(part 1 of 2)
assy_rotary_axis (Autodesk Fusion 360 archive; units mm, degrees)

design "assy_rotary_axis" references "circuit_mount_stepper_simple", "PP_ACTU_N17-Stepper", "PP_BRNG_6808-40x52x7", "rotary_barrel", "HW_M3x20-SHCS", "PP_TRNS_GT2-Pulley-20T-6mm", "HW_M5x10-SHCS", "PP_SWTC_Omron-V154", "HW_M3-Washer", "HW_M3x8-FHCS", "HW_M3x50-SHCS"
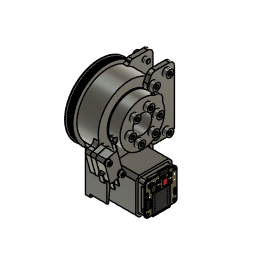
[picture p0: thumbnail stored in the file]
parameter "p_teeth" = 2
parameter "pd_pinion" = 12.7324 (= "nt_pinion * p_teeth / PI")
parameter "pd_drive" = 79.5775 (= "nt_drive * p_teeth / PI")
parameter "c_dist_manuel" = 58
parameter "d63" = 60
sketch "Sketch1" plane through (0, 0, 0) normal (0, 1, 0) x axis (1, 0, 0)
  line L1 (7, 26) -> (0, 26)
  line L2 (7, 20) -> (7, 26)
  line L3 (0, 20) -> (7, 20)
  line L4 (0, 26) -> (0, 20)
  line L5 (25, 20) -> (18, 20)
  line L6 (25, 26) -> (25, 20)
  line L7 (18, 26) -> (25, 26)
  line L8 (18, 20) -> (18, 26)
  line L9 (22.786, 0) -> (0, 0)
  line L10 (-50.1, 36.85) -> (19.9, 36.85)
  line L11 (-50.1, 79.15) -> (-50.1, 36.85)
  line L12 (19.9, 79.15) -> (-50.1, 79.15)
  line L13 (19.9, 36.85) -> (19.9, 79.15)
  line L14 (-50.1, 58) -> (19.9, 58)
  line L15 (25, 37.05) -> (25, 26.05)
  line L16 (0, 26.05) -> (25, 26.05)
  line L17 (25, 37.05) -> (0, 37.05)
  line L18 (0, 37.05) -> (0, 26.05)
  line L19 (7.5, 25.05) -> (6.5, 26.05)
  line L20 (17.5, 25.05) -> (7.5, 25.05)
  line L21 (18.5, 26.05) -> (17.5, 25.05)
  point P6 (18, 20)
  point P1 (0, 0)
  point P10 (0, 0)
  point P16 (19.9, 58)
  point P17 (-50.1, 58)
  point P21 (0, 37.05)
  point P23 (0, 37.05)
  point P18 (25, 26.05)
  point P19 (25, 26.05)
  point P8 (25, 26)
  point P2 (0, 26)
  point P24 (6.5, 26.05)
  point P27 (18.5, 26.05)
  point P4 (7, 20)
  point P5 (0, 20)
  point P12 (19.9, 36.85)
  point P15 (19.9, 79.15)
  point P13 (-50.1, 36.85)
  point P9 (18, 26)
  point P20 (0, 26.05)
  point P22 (25, 37.05)
  point P3 (7, 26)
  horizontal L1
  vertical L2
  horizontal L3
  horizontal L5
  vertical L6
  horizontal L7
  vertical L8
  equal L3 L5
  coincident L3 P6
  coincident P1 L4
  equal L2 L8
  coincident P1 P10
  horizontal L9
  horizontal L10
  vertical L11
  horizontal L12
  midpoint L13 P16
  midpoint L11 P17
  vertical L4
  vertical L15
  vertical L13
  perpendicular L2 L16
  perpendicular L13 L17
  perpendicular L10 L18
  coincident P21 P23
  coincident P18 P19
  coincident P8 L15
  coincident P2 L18
  coincident L16 P24
  parallel L1 L20
  coincident L16 P27
  dimension "d5" distance P4 P5 = 7
  dimension "d6" distance P1 L1 = 26 (= "( 52 / 2 ) * 1 mm")
  dimension "d7" distance P1 P5 = 20 (= "( 40 / 2 ) * 1 mm")
  dimension "d32" distance P12 P15 = 42.3
  dimension "d33" distance P1 P17 = 58 (= "c_dist_manuel")
  dimension "d34" distance P12 P13 = 70
  dimension "d61" distance P4 P6 = 11
  dimension "d140" distance P9 L16 = 0.05
  dimension "d141" distance P20 P23 = 11
  dimension "d150" distance L13 P22 = 5.1
  dimension "d259" angle L19 L20 = 45
  dimension "d260" distance P3 P24 = 0.5
  dimension "d261" distance L16 L20 = 1
  dimension "d262" angle L20 L21 = 45
  dimension "d263" distance L8 P27 = 0.5 (= "d260")
  dimension "d357" distance P18 L18 = 25
revolve "Revolve6" sketch "Sketch1" AlongAngle 360
sketch "Sketch6" plane through (0, 0, 0) normal (1, 0, 0) x axis (0, 1, 0)
  line L1 (21.15, -36.85) -> (-21.15, -36.85)
  line L2 (21.15, -79.15) -> (21.15, -36.85)
  line L3 (-21.15, -79.15) -> (21.15, -79.15)
  line L4 (-21.15, -36.85) -> (-21.15, -79.15)
  line L5 (21.15, -79.15) -> (-21.15, -36.85)
  line L6 (-21.15, -79.15) -> (21.15, -36.85)
  line L7 (0, 0) -> (0, -58)
  line L8 (15.5, -42.5) -> (-15.5, -42.5)
  line L9 (15.5, -73.5) -> (15.5, -42.5)
  line L10 (-15.5, -73.5) -> (15.5, -73.5)
  line L11 (-15.5, -42.5) -> (-15.5, -73.5)
  line L12 (15.4393, -40.5607) -> (-15.5, -42.5)
  line L13 (17.3786, -71.5) -> (-15.5, -42.5)
  line L14 (-13.5607, -73.4393) -> (-15.5, -42.5)
  line L15 (-15.5, -42.5) -> (12.1767, -76.5)
  line L16 (-15.5, -42.5) -> (-18.6616, -73.3384)
  line L17 (-15.5, -42.5) -> (15.3384, -45.6616)
  line L18 (12.4957, -82.7149) -> (-25.4068, -78.8291)
  line L19 (-21.0864, -36.6881) -> (-25.4068, -78.8291)
  line L20 (27, -33.674) -> (-21.0864, -36.6881)
  line L21 (-27, -78.6657) -> (-25.4068, -78.8291)
  line L22 (-27, -25.3713) -> (-27, -78.6657)
  line L23 (24.7149, -70.4957) -> (22.4249, -33.9608)
  line L24 (27, -25.3713) -> (27, -66.8875)
  line L25 (-43.1948, -16.2223) -> (-37.449, -37.6658)
  line L26 (-33.2458, -13.5564) -> (-43.1948, -16.2223)
  line L27 (-27.5, -35) -> (-33.2458, -13.5564)
  line L28 (-37.449, -37.6658) -> (-27.5, -35)
  line L29 (-46.8691, -14.101) -> (-39.5704, -41.3401)
  line L30 (-35.373, -11.0206) -> (-46.8691, -14.101)
  line L31 (-27, -37.9719) -> (-39.5704, -41.3401)
  line L32 (5.2029, -61.6685) -> (32.5183, -22.9283)
  line L33 (-5.2029, -61.6685) -> (-32.5183, -22.9283)
  line L34 (-31.1245, -9.8822) -> (-35.373, -11.0206)
  line L35 (-23.8258, -37.1213) -> (-31.1245, -9.8822)
  line L36 (-27, -37.9719) -> (-23.8258, -37.1213)
  arc A1 centre (-15.5, -42.5) radius 32.75 clockwise from (17.1859, -40.4512) to (17.0792, -45.8401)
  arc A2 centre (15.3384, -45.6616) radius 1.75 clockwise from (17.0792, -45.8401) to (13.5975, -45.4832)
  arc A3 centre (-15.5, -42.5) radius 29.25 clockwise from (13.6927, -40.6702) to (13.5975, -45.4832)
  arc A4 centre (15.4393, -40.5607) radius 1.75 clockwise from (13.6927, -40.6702) to (17.1859, -40.4512)
  arc A5 centre (-15.5, -42.5) radius 31 clockwise from (15.4393, -40.5607) to (15.3384, -45.6616)
  arc A6 centre (-15.5, -42.5) radius 33.0203 clockwise from (9.2638, -64.3425) to (5.3458, -68.1085)
  arc A7 centre (-1.6616, -59.5) radius 11.1 clockwise from (5.3458, -68.1085) to (-8.6691, -50.8915)
  arc A8 centre (-15.5, -42.5) radius 10.8203 clockwise from (-7.3852, -49.6575) to (-8.6691, -50.8915)
  arc A9 centre (0.9393, -57) radius 11.1 clockwise from (-7.3852, -49.6575) to (9.2638, -64.3425)
  arc A10 centre (-15.5, -42.5) radius 21.9203 clockwise from (0.9393, -57) to (-1.6616, -59.5)
  arc A11 centre (-15.5, -42.5) radius 45.5906 clockwise from (18.691, -72.6576) to (13.2815, -77.8572)
  arc A12 centre (12.1767, -76.5) radius 1.75 clockwise from (13.2815, -77.8572) to (11.0719, -75.1428)
  arc A13 centre (-15.5, -42.5) radius 42.0906 clockwise from (16.0661, -70.3424) to (11.0719, -75.1428)
  arc A14 centre (17.3786, -71.5) radius 1.75 clockwise from (16.0661, -70.3424) to (18.691, -72.6576)
  arc A15 centre (-15.5, -42.5) radius 43.8406 clockwise from (17.3786, -71.5) to (12.1767, -76.5)
  arc A16 centre (-15.5, -42.5) radius 32.75 clockwise from (-13.4512, -75.1859) to (-18.8401, -75.0792)
  arc A17 centre (-18.6616, -73.3384) radius 1.75 clockwise from (-18.8401, -75.0792) to (-18.4832, -71.5975)
  arc A18 centre (-15.5, -42.5) radius 29.25 clockwise from (-13.6702, -71.6927) to (-18.4832, -71.5975)
  arc A19 centre (-13.5607, -73.4393) radius 1.75 clockwise from (-13.6702, -71.6927) to (-13.4512, -75.1859)
  arc A20 centre (-15.5, -42.5) radius 31 clockwise from (-13.5607, -73.4393) to (-18.6616, -73.3384)
  circle C1 centre (-15.5, -42.5) radius 1.75
  arc A21 centre (-15.5, -42.5) radius 49 clockwise from (24.7149, -70.4957) to (12.4957, -82.7149)
  arc A22 centre (-15.5, -42.5) radius 49 clockwise from (27, -66.8875) to (24.7149, -70.4957)
  circle C2 centre (0, 0) radius 39.7887
  circle C3 centre (0, 0) radius 26.05
  circle C4 centre (0, 0) radius 37.05
  circle C5 centre (-27.5, -35) radius 1.25
  circle C6 centre (-43.1948, -16.2223) radius 1.25
  circle C7 centre (-43.1948, -16.2223) radius 3
  circle C8 centre (0, -58) radius 6.3662
  circle C9 centre (-27.5, -35) radius 3
  circle C10 centre (-27.5, -35) radius 1.75
  circle C11 centre (-43.1948, -16.2223) radius 1.75
  point P6 (0, -58)
  point P8 (0, -58)
  point P7 (0, 0)
  point P9 (0, 0)
  point P12 (15.5, -73.5)
  point P10 (-15.5, -42.5)
  point P13 (-15.5, -73.5)
  point P20 (-15.5, -42.5)
  point P27 (-15.5, -42.5)
  point P34 (-15.5, -42.5)
  point P41 (-15.5, -42.5)
  point P43 (-15.5, -42.5)
  point P18 (15.4393, -40.5607)
  point P44 (15.4393, -40.5607)
  point P42 (-15.5, -42.5)
  point P45 (-15.5, -42.5)
  point P32 (17.3786, -71.5)
  point P46 (17.3786, -71.5)
  point P47 (-15.5, -42.5)
  point P39 (-13.5607, -73.4393)
  point P48 (-13.5607, -73.4393)
  point P11 (15.5, -42.5)
  point P25 (0.9393, -57)
  point P33 (12.1767, -76.5)
  point P49 (12.1767, -76.5)
  point P50 (-15.5, -42.5)
  point P40 (-18.6616, -73.3384)
  point P51 (-18.6616, -73.3384)
  point P52 (-15.5, -42.5)
  point P19 (15.3384, -45.6616)
  point P53 (15.3384, -45.6616)
  point P54 (-15.5, -42.5)
  point P26 (-1.6616, -59.5)
  point P57 (-15.5, -42.5)
  point P60 (-21.0864, -36.6881)
  point P64 (22.4249, -33.9608)
  point P66 (19.1482, -77.1482)
  point P58 (24.7149, -70.4957)
  point P65 (24.7149, -70.4957)
  point P61 (27, -33.674)
  point P69 (-15.5, -42.5)
  point P67 (27, -66.8875)
  point P70 (27, -66.8875)
  point P71 (0, 0)
  point P68 (27, -25.3713)
  point P63 (-27, -25.3713)
  point P59 (-21.0864, -36.6881)
  point P76 (-27.5, -35)
  point P77 (-27.5, -35)
  point P74 (-43.1948, -16.2223)
  point P78 (-43.1948, -16.2223)
  point P80 (-35.373, -11.0206)
  point P83 (-27, -37.9719)
  point P84 (0, -58)
  point P85 (32.5183, -22.9283)
  point P86 (5.2029, -61.6685)
  point P87 (-32.5183, -22.9283)
  point P88 (-5.2029, -61.6685)
  point P4 (21.15, -79.15)
  point P5 (-21.15, -79.15)
  point P1 (0, 0)
  point P73 (-37.449, -37.6658)
  point P75 (-33.2458, -13.5564)
  point P81 (-43.1948, -16.2223)
  horizontal L1
  perpendicular L1 L2
  parallel L1 L3
  parallel L2 L4
  coincident L5 P6
  coincident L6 P6
  equal L2 L3
  coincident P6 P8
  coincident P7 P9
  vertical L7
  horizontal L8
  vertical L9
  horizontal L10
  vertical L11
  coincident L5 P12
  coincident L5 P10
  coincident L6 P13
  tangent A1 A2
  tangent A2 A3
  tangent A3 A4
  tangent A1 A4
  coincident P10 P20
  tangent A6 A7
  tangent A7 A8
  tangent A8 A9
  tangent A6 A9
  coincident P20 P27
  tangent A11 A12
  tangent A12 A13
  tangent A13 A14
  tangent A11 A14
  coincident P27 P34
  tangent A16 A17
  tangent A17 A18
  tangent A18 A19
  tangent A16 A19
  coincident P34 P41
  concentric A11 C1
  coincident P34 P43
  coincident P18 P44
  coincident P42 P45
  coincident P32 P46
  coincident P41 P47
  coincident P39 P48
  coincident P11 A5
  coincident P6 A10
  coincident P13 A20
  coincident P12 A15
  coincident P25 L13
  coincident P33 P49
  coincident P20 P50
  coincident P40 P51
  coincident P27 P52
  coincident P19 P53
  coincident P20 P54
  equal A4 A14
  equal A14 A19
  equal A19 C1
  coincident P26 L15
  perpendicular L12 L14
  perpendicular L16 L17
  parallel L17 L18
  coincident P42 P57
  parallel L16 L19
  coincident L19 P60
  parallel L12 L20
  perpendicular L19 L21
  vertical L22
  coincident L20 P64
  perpendicular L20 L23
  midpoint A21 P66
  coincident L5 P66
  coincident P58 P65
  vertical L24
  coincident P61 L24
  coincident P57 P69
  coincident P67 P70
  coincident P7 P71
  coincident P68 C4
  coincident P63 C4
  coincident P59 P60
  perpendicular L25 L26
  parallel L25 L27
  parallel L26 L28
  coincident P76 P77
  coincident P74 P78
  equal C5 C6
  perpendicular L26 L29
  coincident C4 P80
  perpendicular L29 L30
  concentric C6 C7
  coincident L22 P83
  perpendicular L29 L31
  coincident P6 P84
  coincident C2 P85
  coincident C8 P86
  tangent C8 L32
  tangent C2 L32
  coincident C2 P87
  coincident C8 P88
  tangent C8 L33
  tangent C2 L33
  parallel L30 L34
  parallel L31 L36
  parallel L27 L35
  concentric C5 C9
  tangent L31 C9
  tangent L35 C9
  concentric C9 C10
  concentric C7 C11
  equal C10 C11
  dimension "d151" distance P6 P7 = 58 (= "c_dist_manuel")
  dimension "d152" distance P4 P5 = 42.3
  dimension "d153" distance P10 P11 = 31
  dimension "d154" diameter C1 = 3.5
  dimension "d156" radius A9 = 11.1 (= "( 22.2 / 2 ) * 1 mm")
  dimension "d157" distance P6 P25 = 1
  dimension "d158" distance P6 P26 = 1.5
  dimension "d159" angle L15 L17 = 45
  dimension "d160" radius A21 = 49
  dimension "d161" distance P40 L18 = 6.15 (= "( ( 42.3 - 31 ) / 2 ) * 1 mm + 0.5 mm")
  dimension "d162" distance L16 L19 = 6.15 (= "d161")
  dimension "d163" angle L12 L13 = 45
  dimension "d164" distance P20 L20 = 6.15 (= "d161")
  dimension "d166" distance P9 L22 = 27
  dimension "d167" distance P1 L24 = 27
  dimension "d264" diameter C2 = 79.5775 (= "pd_drive")
  dimension "d286" distance P73 P74 = 22.2
  dimension "d288" distance P74 P75 = 10.3
  dimension "d289" diameter C6 = 2.5
  dimension "d290" angle L7 L27 = 15
  dimension "d291" distance P71 P77 = 35
  dimension "d292" distance P1 P77 = 27.5
  dimension "d293" diameter C7 = 6
  dimension "d294" distance L29 P81 = 3
  dimension "d295" distance L30 P81 = 3 (= "d294")
  dimension "d303" distance P73 L31 = 3 (= "d294")
  dimension "d435" diameter C8 = 12.7324 (= "( 20 * 2 / PI ) * 1 mm")
  dimension "d439" diameter C11 = 3.5
extrude "Extrude8" add sketch "Sketch6" profile of L19 L20 L21 L22 L23 L24 A22 C4 to an object
extrude "Extrude20" cut sketch "Sketch6" profile of L20 C4 to an object
extrude "Extrude19" add sketch "Sketch6" profile of A1 A2 A3 A4 A6 A7 A8 A9 A11 A12 A13 A14 A16 A17 A18 A19 C1 L18 A21 L19 L20 L23 along normal blind 5
chamfer "Chamfer4" distance 1.5
extrude "Extrude21" sketch "Sketch6" profile of L22 C4 C5 C6 L29 L30 L31 blind -6
extrude "Extrude22" sketch "Sketch6" profile of L22 C5 to an object offset 0.5
chamfer "Chamfer5" distance 1.25
chamfer "Chamfer6" distance 0.5
sketch "Sketch10" plane through (0, 0, 0) normal (-1, 0, 0) x axis (0, -1, 0)
  line L1 (27, -78.6657) -> (-12.4957, -82.7149)
  line L2 (27, -25.3713) -> (27, -78.6657)
  line L3 (-27, -66.8875) -> (-27, -25.3713)
  line L4 (-27, 50) -> (-47, 50)
  line L5 (-27, -90) -> (-27, 50)
  line L6 (-47, -90) -> (-27, -90)
  line L7 (-47, 50) -> (-47, -90)
  line L8 (-37, -90) -> (-37, 50)
  line L9 (-21.362, 37) -> (-47, 37)
  line L10 (-47, -37) -> (-27, -37)
  line L11 (-21.362, -37) -> (-27, -37)
  line L12 (-13.275, -22.993) -> (-21.362, -37)
  line L13 (-27, 0) -> (0, 0)
  line L14 (-21.362, 37) -> (-13.275, 22.993)
  circle C1 centre (15.5, -42.5) radius 3.25
  arc A1 centre (15.5, -42.5) radius 40.5906 clockwise from (-10.125, -73.9795) to (-14.9412, -69.3502)
  arc A2 centre (-12.1767, -76.5) radius 3.25 clockwise from (-10.125, -73.9795) to (-14.2284, -79.0205)
  arc A3 centre (15.5, -42.5) radius 47.0906 clockwise from (-14.2284, -79.0205) to (-19.8159, -73.6498)
  arc A4 centre (-17.3786, -71.5) radius 3.25 clockwise from (-19.8159, -73.6498) to (-14.9412, -69.3502)
  arc A5 centre (0, 0) radius 37.05 clockwise from (-27, -25.3713) to (27, -25.3713)
  arc A6 centre (15.5, -42.5) radius 49 clockwise from (-12.4957, -82.7149) to (-27, -66.8875)
  arc A7 centre (1.6616, -59.5) radius 11.1 clockwise from (8.6691, -50.8915) to (-5.3458, -68.1085)
  arc A8 centre (15.5, -42.5) radius 33.0203 clockwise from (-5.3458, -68.1085) to (-9.2638, -64.3425)
  arc A9 centre (-0.9393, -57) radius 11.1 clockwise from (-9.2638, -64.3425) to (7.3852, -49.6575)
  arc A10 centre (15.5, -42.5) radius 10.8203 clockwise from (8.6691, -50.8915) to (7.3852, -49.6575)
  arc A11 centre (15.5, -42.5) radius 27.75 clockwise from (-12.1053, -45.3302) to (-12.1956, -40.764)
  arc A12 centre (-15.3384, -45.6616) radius 3.25 clockwise from (-12.1053, -45.3302) to (-18.5714, -45.9931)
  arc A13 centre (15.5, -42.5) radius 34.25 clockwise from (-18.5714, -45.9931) to (-18.6829, -40.3574)
  arc A14 centre (-15.4393, -40.5607) radius 3.25 clockwise from (-18.6829, -40.3574) to (-12.1956, -40.764)
  arc A15 centre (13.5607, -73.4393) radius 3.25 clockwise from (13.3574, -76.6829) to (13.764, -70.1956)
  arc A16 centre (15.5, -42.5) radius 27.75 clockwise from (18.3302, -70.1053) to (13.764, -70.1956)
  arc A17 centre (18.6616, -73.3384) radius 3.25 clockwise from (18.3302, -70.1053) to (18.9931, -76.5714)
  arc A18 centre (15.5, -42.5) radius 34.25 clockwise from (18.9931, -76.5714) to (13.3574, -76.6829)
  circle C2 centre (0, 0) radius 26.55
  circle C3 centre (-37, -30) radius 2.75
  circle C4 centre (-37, 0) radius 2.75
  circle C5 centre (-37, 30) radius 2.75
  circle C6 centre (-21.1923, -24.7061) radius 2.75
  circle C7 centre (-21.1923, -24.7061) radius 2.2
  circle C8 centre (-21.1923, -24.7061) radius 6
  circle C9 centre (-21.1923, 24.7061) radius 2.75
  circle C10 centre (-21.1923, 24.7061) radius 2.2
  circle C11 centre (-21.1923, 24.7061) radius 6
  circle C12 centre (-37, 30) radius 4.5
  point P12 (-27, -25.3713)
  point P37 (-37, 50)
  point P38 (-37, -90)
  point P39 (-47, 37)
  point P40 (-27, -37)
  point P41 (-47, -37)
  point P42 (-37, -30)
  point P43 (-37, 0)
  point P44 (-37, 30)
  point P48 (-13.275, -22.993)
  point P1 (0, 0)
  point P49 (0, 0)
  point P50 (-27, 0)
  point P55 (-13.275, 22.993)
  point P33 (-47, 50)
  point P34 (-27, 50)
  point P13 (0, 0)
  horizontal L4
  vertical L5
  horizontal L6
  vertical L7
  coincident P12 L5
  midpoint L4 P37
  midpoint L6 P38
  coincident L7 P39
  perpendicular L7 L9
  coincident L5 P40
  coincident L7 P41
  perpendicular L7 L10
  coincident L8 P42
  coincident L8 P43
  coincident L8 P44
  equal C4 C5
  equal C3 C4
  concentric C6 C7
  perpendicular L5 L11
  coincident C2 P48
  coincident P1 L12
  coincident P1 P49
  coincident L5 P50
  perpendicular L5 L13
  concentric C7 C8
  equal C3 C6
  symmetric C6 L13 C9
  symmetric C7 L13 C10
  symmetric L13 C8 C11
  coincident C2 P55
  tangent C11 L14
  coincident P1 L14
  tangent C2 C8
  tangent L12 C8
  concentric C5 C12
  coincident P43 L13
  dimension "d358" distance P33 P34 = 20
  dimension "d359" distance P13 L4 = 50
  dimension "d360" distance P13 L6 = 90
  dimension "d368" diameter C3 = 5.5
  dimension "d369" distance P42 P43 = 30
  dimension "d370" distance P43 P44 = 30 (= "d369")
  dimension "d371" distance P39 P44 = 7
  dimension "d372" distance L10 P42 = 7
  dimension "d375" angle L12 L13 = 60
  dimension "d376" diameter C7 = 4.4
  dimension "d377" diameter C8 = 12
  dimension "d408" diameter C12 = 9
extrude "Extrude23" cut sketch "Sketch10" profile of A5 L3 L5 L7 L9 L10 no distance stored from offset -5
extrude "Extrude24" add sketch "Sketch10" profile of A5 L3 L5 L7 L9 L10 C3 C5 against normal blind 5
extrude "Extrude25" cut sketch "Sketch10" profile of C3 C5 no distance stored
extrude "Extrude26" cut sketch "Sketch10" profile of C7 C10 no distance stored
extrude "Extrude27" sketch "Sketch10" profile of A5 L3 C2 L5 L7 L9 L10 C3 C4 C5 C6 L11 L12 C9 L14 blind -5 from offset -0.1 bodies "rotary_body_cap"
fillet "Fillet18" radius 6
fillet "Fillet19" radius 6
extrude "Extrude28" sketch "Sketch6" profile of L22 C4 L29 L30 L31 L34 L35 L36 C10 C11 blind 6 from offset 0.1 bodies "rotary_limit_shim"
component_insert "Component Insert9"
component_insert "Component Insert10"
joint "Assemble7" alignAngle 180 alignOffsetX 0 alignOffsetY 0 alignOffsetZ 0
joint "Assemble8" alignAngle 180 alignOffsetX 0 alignOffsetY 0 alignOffsetZ 0
component_insert "Component Insert1"
joint "Assemble1" alignAngle 0 alignOffsetX 0 alignOffsetY 0 alignOffsetZ 0
component_insert "Component Insert6"
joint "Assemble4" alignAngle 180 alignOffsetX 0 alignOffsetY 0 alignOffsetZ 0
component_insert "Component Insert7"
joint "Assemble5" alignAngle -195 alignOffsetX 0 alignOffsetY 0 alignOffsetZ 0
component_insert "Component Insert8"
joint "Assemble6" alignAngle 0 alignOffsetX 0 alignOffsetY 0 alignOffsetZ -2.5
component_insert "Component Insert11"
component_insert "Component Insert12"
component_insert "Component Insert13"
component_insert "Component Insert14"
joint "Assemble9" alignAngle 180 alignOffsetX 0 alignOffsetY 0 alignOffsetZ 0
joint "Assemble10" alignAngle 180 alignOffsetX 0 alignOffsetY 0 alignOffsetZ -5
joint "Assemble11" alignAngle 180 alignOffsetX 0 alignOffsetY 0 alignOffsetZ -5
joint "Assemble12" alignAngle 180 alignOffsetX 0 alignOffsetY 0 alignOffsetZ -5
component_insert "Component Insert15"
component_insert "Component Insert16"
joint "Assemble13" alignAngle 0 alignOffsetX 0 alignOffsetY 0 alignOffsetZ 0
joint "Assemble14" alignAngle 0 alignOffsetX 0 alignOffsetY 0 alignOffsetZ 0
component_insert "Component Insert17"
component_insert "Component Insert18"
joint "Assemble15" alignAngle 0 alignOffsetX 0 alignOffsetY 0 alignOffsetZ 0
joint "Assemble16" alignAngle 0 alignOffsetX 0 alignOffsetY 0 alignOffsetZ 0
fillet "Fillet10" radius 4
fillet "Fillet11" radius 10
fillet "Fillet12" radius 1
fillet "Fillet13" radius 5
fillet "Fillet14" radius 1
fillet "Fillet15" radius 1
fillet "Fillet16" radius 3
fillet "Fillet17" radius 5
fillet "Fillet20" radius 6
component_insert "Component Insert19"
joint "Assemble17" alignAngle 90 alignOffsetX 0 alignOffsetY 0 alignOffsetZ 0
component_insert "Component Insert23"
joint "Assemble20" alignAngle 90 alignOffsetX 0 alignOffsetY 0 alignOffsetZ 0
component_insert "Component Insert24"
joint "Assemble21" alignAngle 0 alignOffsetX 0 alignOffsetY 0 alignOffsetZ 0
fillet "Fillet21" radius 3
component_insert "Component Insert25"
component_insert "Component Insert26"
component_insert "Component Insert27"
component_insert "Component Insert28"
component_insert "Component Insert29"
joint "Assemble22" alignAngle 0 alignOffsetX 0 alignOffsetY 0 alignOffsetZ 0
joint "Assemble23" alignAngle 0 alignOffsetX 0 alignOffsetY 0 alignOffsetZ 0
joint "Assemble24" alignAngle 0 alignOffsetX 0 alignOffsetY 0 alignOffsetZ 0
joint "Assemble25" alignAngle 0 alignOffsetX 0 alignOffsetY 0 alignOffsetZ 0
joint "Assemble26" alignAngle 0 alignOffsetX 0 alignOffsetY 0 alignOffsetZ 0
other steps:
joint_origin "JointOrigin5"
joint_origin "JointOrigin6"
joint_origin "JointOrigin10"
joint_origin "JointOrigin11"
joint_origin "JointOrigin12"
joint_origin "JointOrigin15"
joint_origin "JointOrigin16"
joint_origin "JointOrigin17"
joint_origin "JointOrigin18"
joint_origin "JointOrigin19"
joint_origin "JointOrigin20"
joint_origin "JointOrigin21"
named bodies: "rotary_body", "rotary_body_cap", "rotary_limit_shim"

design "rotary_barrel" references "HW_M5x25-SHCS"
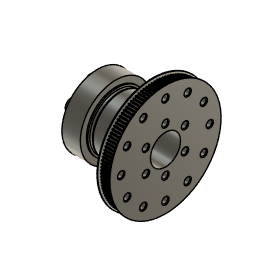
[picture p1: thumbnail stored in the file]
parameter "p_teeth" = 2
parameter "pd_pinion" = 12.7324 (= "nt_pinion * p_teeth / PI")
parameter "pd_drive" = 79.5775 (= "nt_drive * p_teeth / PI")
parameter "c_dist_manuel" = 75
sketch "Sketch1" plane through (0, 0, 0) normal (0, 1, 0) x axis (1, 0, 0)
  line L1 (7, 26) -> (0, 26)
  line L2 (7, 20) -> (7, 26)
  line L3 (0, 20) -> (7, 20)
  line L4 (0, 26) -> (0, 20)
  line L5 (25, 20) -> (18, 20)
  line L6 (25, 26) -> (25, 20)
  line L7 (18, 26) -> (25, 26)
  line L8 (18, 20) -> (18, 26)
  line L9 (35.5, 11.05) -> (2.5, 11.05)
  line L10 (35.5, 39.7887) -> (26, 39.7887)
  line L11 (26, 21.5) -> (25, 21.5)
  line L12 (26, 40.7887) -> (26, 21.5)
  line L13 (26.5, 40.7887) -> (26, 40.7887)
  line L14 (27.9434, 38.2887) -> (26.5, 40.7887)
  line L15 (33.5566, 38.2887) -> (27.9434, 38.2887)
  line L16 (35, 40.7887) -> (33.5566, 38.2887)
  line L17 (30.75, 38.2887) -> (30.75, 39.7887)
  line L18 (35, 38.2887) -> (35, 40.7887)
  line L19 (33.5566, 38.2887) -> (35, 38.2887)
  line L20 (26, 38.2887) -> (27.9434, 38.2887)
  line L21 (25, 20.05) -> (25, 21.5)
  line L22 (2.5, 20.05) -> (25, 20.05)
  line L23 (2.5, 11.05) -> (2.5, 20.05)
  line L24 (26, 38.2887) -> (26, 21.5)
  line L25 (35.5, 11.05) -> (35.5, 39.7887)
  line L26 (2, 11.05) -> (2, 20.05)
  line L27 (-14.5, 11.05) -> (2, 11.05)
  line L28 (-14.5, 26) -> (-14.5, 11.05)
  line L29 (-1, 26) -> (-14.5, 26)
  line L30 (-1, 21.5) -> (-1, 26)
  line L31 (0, 21.5) -> (-1, 21.5)
  line L32 (0, 20.05) -> (0, 21.5)
  line L33 (2, 20.05) -> (0, 20.05)
  line L34 (35.5, 40.7887) -> (35, 40.7887)
  line L35 (35.5, 39.7887) -> (35.5, 40.7887)
  line L36 (35.5, 14.35) -> (2.5, 14.35)
  line L37 (2.5, 16.55) -> (35.5, 16.55)
  line L38 (-14.5, 16.55) -> (2, 16.55)
  line L39 (-12.025, 13.925) -> (-14.5, 11.45)
  line L40 (2, 13.925) -> (-12.025, 13.925)
  line L41 (26, 32.5) -> (35.5, 32.5)
  line L42 (35.5, 34.7) -> (26, 34.7)
  line L43 (-14.5, 13.925) -> (-12.025, 13.925)
  point P6 (18, 20)
  point P1 (0, 0)
  point P13 (25, 21.5)
  point P20 (30.75, 39.7887)
  point P21 (30.75, 38.2887)
  point P11 (26, 39.7887)
  point P22 (27.2217, 39.5387)
  point P23 (34.2783, 39.5387)
  point P18 (33.5566, 38.2887)
  point P25 (33.5566, 38.2887)
  point P26 (26, 38.2887)
  point P27 (25, 20.05)
  point P10 (35.5, 11.05)
  point P30 (35.5, 11.05)
  point P31 (2, 20.05)
  point P39 (2, 20.05)
  point P32 (2, 11.05)
  point P5 (0, 20)
  point P12 (35.5, 39.7887)
  point P41 (35.5, 39.7887)
  point P42 (2.5, 14.35)
  point P45 (2.5, 16.55)
  point P46 (2, 16.55)
  point P47 (-14.5, 16.55)
  point P48 (-14.5, 11.45)
  point P50 (2, 13.925)
  point P51 (35.5, 32.5)
  point P54 (35.5, 34.7)
  point P53 (26, 34.7)
  point P52 (26, 32.5)
  point P44 (35.5, 16.55)
  point P43 (35.5, 14.35)
  point P55 (-14.5, 13.925)
  point P4 (7, 20)
  point P14 (26, 21.5)
  point P15 (26, 40.7887)
  point P16 (26.5, 40.7887)
  point P7 (25, 20)
  point P3 (7, 26)
  point P9 (18, 26)
  point P28 (2.5, 20.05)
  point P29 (2.5, 11.05)
  point P36 (-1, 21.5)
  point P37 (0, 21.5)
  point P19 (35, 40.7887)
  point P40 (35.5, 40.7887)
  point P33 (-14.5, 11.05)
  point P38 (0, 20.05)
  horizontal L1
  vertical L2
  horizontal L3
  horizontal L5
  vertical L6
  horizontal L7
  vertical L8
  equal L3 L5
  coincident L3 P6
  coincident P1 L4
  equal L2 L8
  horizontal L9
  vertical L4
  horizontal L10
  coincident L6 P13
  perpendicular L6 L11
  perpendicular L10 L12
  perpendicular L12 L13
  perpendicular L12 L15
  midpoint L10 P20
  midpoint L15 P21
  vertical L17
  coincident P11 L12
  midpoint L14 P22
  midpoint L16 P23
  perpendicular L18 L19
  coincident P18 P25
  coincident L12 P26
  perpendicular L12 L20
  coincident L6 P27
  perpendicular L4 L22
  perpendicular L9 L23
  equal L14 L16
  vertical L18
  perpendicular L10 L25
  coincident P10 P30
  perpendicular L5 L26
  perpendicular L9 L28
  perpendicular L28 L29
  perpendicular L29 L30
  perpendicular L30 L31
  perpendicular L31 L32
  perpendicular L30 L33
  coincident P31 P39
  coincident L22 P31
  coincident L9 P32
  coincident P5 L32
  coincident P13 L31
  horizontal L27
  perpendicular L18 L34
  perpendicular L34 L35
  coincident P12 P41
  coincident L23 P42
  perpendicular L23 L36
  coincident L23 P45
  perpendicular L23 L37
  coincident L26 P46
  coincident L28 P47
  perpendicular L28 L38
  coincident L28 P48
  coincident L26 P50
  perpendicular L26 L40
  coincident P45 L38
  coincident L25 P51
  perpendicular L25 L41
  coincident L25 P54
  perpendicular L25 L42
  coincident L12 P53
  coincident L12 P52
  coincident L25 P44
  coincident L25 P43
  coincident L28 P55
  perpendicular L28 L43
  dimension "d5" distance P4 P5 = 7
  dimension "d6" distance P1 L1 = 26 (= "( 52 / 2 ) * 1 mm")
  dimension "d7" distance P1 P5 = 20 (= "( 40 / 2 ) * 1 mm")
  dimension "d62" distance P1 L10 = 39.7887 (= "pd_drive / 2")
  dimension "d63" angle L13 L14 = 60
  dimension "d66" distance P13 P14 = 1
  dimension "d67" distance L10 L13 = 1
  dimension "d68" distance L10 L15 = 1.5
  dimension "d69" distance P15 P16 = 0.5
  dimension "d71" distance P7 L11 = 1.5
  dimension "d72" distance P6 L22 = 0.05
  dimension "d81" angle L15 L16 = 120 (= "180 deg - d63")
  dimension "d133" distance P15 L18 = 9
  dimension "d223" distance P3 P9 = 11
  dimension "d224" distance L23 P32 = 0.5
  dimension "d225" distance P28 P29 = 9
  dimension "d227" distance P36 P37 = 1
  dimension "d228" distance P1 L29 = 26 (= "( 52 / 2 ) * 1 mm")
  dimension "d229" distance P19 P40 = 0.5
  dimension "d237" distance P10 L28 = 50
  dimension "d238" distance P32 P33 = 16.5
  dimension "d240" distance L36 P45 = 2.2 (= "( 4.4 / 2 ) * 1 mm")
  dimension "d242" distance L38 L40 = 2.625 (= "( 5.25 / 2 ) * 1 mm")
  dimension "d243" angle L39 L40 = 45
  dimension "d244" distance P47 P48 = 5.1 (= "( 10.2 / 2 ) * 1 mm")
  dimension "d245" distance P33 L38 = 5.5
  dimension "d250" distance L41 P54 = 2.2 (= "( 4.4 / 2 ) * 1 mm")
  dimension "d251" distance P1 L41 = 32.5
  dimension "d307" distance P13 P37 = 25
  dimension "d308" distance L26 P38 = 2
revolve "Revolve1" sketch "Sketch1" AlongAngle 360 bodies "rotary_barrel_toothed", "rotary_barrel_cap"
sketch "Sketch5" plane through (26, 0, 0) normal (-1, 0, 0) x axis (0, -1, 0)
  line L1 (0, -39.7887) -> (0, 0)
  line L2 (-0.9999, -39.7762) -> (0, 0)
  circle C1 centre (0, 0) radius 21.5
  circle C2 centre (0, 0) radius 39.7887
  circle C3 centre (0, 0) radius 39.5347
  arc A1 centre (0, -39.3347) radius 0.55 clockwise from (-0.4889, -39.0828) to (0, -38.7847)
  arc A2 centre (0.4, -39.5409) radius 1 clockwise from (-0.5899, -39.3991) to (-0.4889, -39.0828)
  arc A3 centre (-0.7384, -39.3778) radius 0.15 clockwise from (-0.5899, -39.3991) to (-0.7412, -39.5278)
  point P1 (0, 0)
  point P4 (0, 0)
  point P5 (0, -39.7887)
  point P3 (0, 0)
  point P6 (0, 0)
  point P7 (-0.9999, -39.7762)
  point P9 (0, -38.7847)
  point P13 (-0.7412, -39.5278)
  point P15 (0, -39.5347)
  point P8 (0, -39.3347)
  point P11 (0.4, -39.5409)
  concentric C1 C3
  coincident P1 P4
  coincident C2 P5
  vertical L1
  coincident P3 P6
  coincident C2 P7
  coincident L1 P9
  tangent A1 A2
  tangent A2 A3
  coincident C3 P13
  coincident L1 P15
  coincident C3 P15
  coincident L1 P8
  tangent C3 A3
  dimension "d116" distance C2 C3 = 0.254
  dimension "d117" angle L1 L2 = 1.44 (= "( 180 / nt_drive ) * 1 deg")
  dimension "d118" radius A1 = 0.55
  dimension "d119" radius A2 = 1
  dimension "d120" distance L1 P11 = 0.4
  dimension "d121" radius A3 = 0.15
  dimension "d122" distance P9 P15 = 0.75
extrude "Extrude6" new body sketch "Sketch5" profile of C2 C3 L1 L2 A1 A2 A3 to an object
offset_faces "OffsetFaces1" distance 0.05
mirror "Mirror2" mirrorStitchTolerance 0.1
circular_pattern "C-Pattern3" TotalAngle 360
combine "Combine3"
combine "Combine4"
revolve "Revolve5" sketch "Sketch1" AlongAngle 360
sketch "Sketch8" plane through (-14.5, 0, 0) normal (-1, 0, 0) x axis (0, -1, 0)
  line L1 (-29, 0) -> (0, 0)
  circle C1 centre (0, 0) radius 11.05
  circle C2 centre (0, 0) radius 26
  arc A1 centre (-21, 0) radius 8 clockwise from (-25.0714, -6.8865) to (-25.0714, 6.8865)
  point P4 (-25.0714, 6.8865)
  point P3 (-25.0714, -6.8865)
  point P1 (0, 0)
  point P6 (0, 0)
  point P8 (-26, 0)
  point P7 (-29, 0)
  point P5 (-21, 0)
  coincident C2 P4
  coincident C2 P3
  coincident P1 P6
  horizontal L1
  coincident L1 P8
  coincident C2 P8
  coincident A1 P7
  coincident P5 L1
  dimension "d231" distance P7 P8 = 3
  dimension "d232" radius A1 = 8
extrude "Extrude13" add sketch "Sketch8" profile of C2 A1 against normal blind 3.6
fillet "Fillet2" radius 5
revolve "Revolve7" sketch "Sketch1" AlongAngle 360
chamfer "Chamfer4" distance 0.5
circular_pattern "C-Pattern9" TotalAngle 360
revolve "Revolve8" sketch "Sketch1" AlongAngle 360
chamfer "Chamfer3" distance 0.5
circular_pattern "C-Pattern8" countU 12 TotalAngle 360
component_insert "Component Insert14"
component_insert "Component Insert15"
component_insert "Component Insert16"
component_insert "Component Insert17"
component_insert "Component Insert18"
component_insert "Component Insert19"
joint "Assemble25" alignAngle 0 alignOffsetX 0 alignOffsetY 0 alignOffsetZ 0
joint "Assemble26" alignAngle 0 alignOffsetX 0 alignOffsetY 0 alignOffsetZ 0
joint "Assemble27" alignAngle 180 alignOffsetX 0 alignOffsetY 0 alignOffsetZ 0
joint "Assemble28" alignAngle 0 alignOffsetX 0 alignOffsetY 0 alignOffsetZ 0
joint "Assemble29" alignAngle 0 alignOffsetX 0 alignOffsetY 0 alignOffsetZ 0
joint "Assemble30" alignAngle 0 alignOffsetX 0 alignOffsetY 0 alignOffsetZ 0
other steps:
joint_origin "JointOrigin26"
joint_origin "JointOrigin27"
joint_origin "JointOrigin28"
joint_origin "JointOrigin29"
joint_origin "JointOrigin30"
joint_origin "JointOrigin31"
named bodies: "rotary_barrel_toothed", "rotary_barrel_cap"

design "HW_M5x25-SHCS"
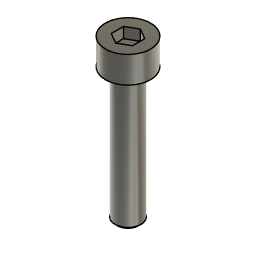
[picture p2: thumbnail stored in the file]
sketch "Sketch1" plane through (0, 0, 0) normal (0, 1, 0) x axis (1, 0, 0)
  line L1 (0, 25) -> (0, -5)
  line L2 (1.95, 25) -> (0, 25)
  line L3 (2.45, 24.5) -> (1.95, 25)
  line L4 (2.45, 0) -> (2.45, 24.5)
  line L5 (4.25, 0) -> (2.45, 0)
  line L6 (4.25, -5) -> (4.25, 0)
  line L7 (0, -5) -> (4.25, -5)
  point P1 (0, 0)
  point P4 (1.95, 25)
  point P5 (2.45, 24.5)
  point P3 (0, 25)
  point P7 (4.25, 0)
  point P8 (4.25, -5)
  point P2 (0, -5)
  vertical L1
  perpendicular L1 L2
  perpendicular L2 L4
  perpendicular L4 L5
  perpendicular L5 L6
  horizontal L7
  coincident P1 L1
  coincident P1 L5
  dimension "d1" distance P1 L2 = 25
  dimension "d2" angle L2 L3 = 45
  dimension "d3" distance P4 P5 = 0.5
  dimension "d4" distance P3 L4 = 2.45 (= "( 4.9 / 2 ) * 1 mm")
  dimension "d5" distance P7 P8 = 5
  dimension "d6" distance P2 P8 = 4.25 (= "( 8.5 / 2 ) * 1 mm")
revolve "Revolve1" sketch "Sketch1" AlongAngle 360
sketch "Sketch2" plane through (0, 0, 5) normal (0, 0, 1) x axis (-1, 0, 0)
  line L1 (0, -2.3094) -> (-2, -1.1547)
  line L2 (2, -1.1547) -> (0, -2.3094)
  line L3 (2, 1.1547) -> (2, -1.1547)
  line L4 (0, 2.3094) -> (2, 1.1547)
  line L5 (-2, 1.1547) -> (0, 2.3094)
  line L6 (-2, -1.1547) -> (-2, 1.1547)
  circle C1 centre (0, 0) radius 4.25
  point P1 (0, 0)
  point P9 (0, 0)
  point P5 (2, -1.1547)
  coincident P1 P9
  vertical L6
  dimension "d8" distance P5 L6 = 4
extrude "Extrude1" cut sketch "Sketch2" profile of L1 L2 L3 L4 L5 L6 against normal blind 2

design "HW_M3x8-FHCS"
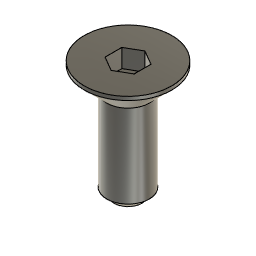
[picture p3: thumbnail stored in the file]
sketch "Sketch1" plane through (0, 0, 0) normal (0, 1, 0) x axis (1, 0, 0)
  line L1 (0, 8) -> (0, 0)
  line L2 (0.95, 8) -> (0, 8)
  line L3 (1.45, 7.5) -> (0.95, 8)
  line L4 (1.45, 1.8) -> (1.45, 7.5)
  line L5 (3, 0.25) -> (1.45, 1.8)
  line L6 (3, 0) -> (3, 0.25)
  line L7 (0, 0) -> (3, 0)
  point P1 (0, 0)
  point P2 (0, 0)
  point P9 (0, 0)
  point P3 (0, 8)
  point P4 (0.95, 8)
  point P8 (3, 0)
  point P7 (3, 0.25)
  coincident P1 P2
  vertical L1
  perpendicular L1 L2
  perpendicular L2 L4
  parallel L3 L5
  parallel L4 L6
  perpendicular L6 L7
  coincident P1 P9
  dimension "d1" distance P3 L4 = 1.45 (= "( 2.9 / 2 ) * 1 mm")
  dimension "d3" angle L2 L3 = 45
  dimension "d5" distance P4 L4 = 0.5
  dimension "d6" distance P2 P3 = 8
  dimension "d7" distance P8 P9 = 3 (= "( 6 / 2 ) * 1 mm")
  dimension "d9" distance P7 P8 = 0.25
revolve "Revolve1" sketch "Sketch1" AlongAngle 360
sketch "Sketch2" plane through (0, 0, 0) normal (0, 0, 1) x axis (-1, 0, 0)
  line L1 (0, -1.1547) -> (-1, -0.5774)
  line L2 (1, -0.5774) -> (0, -1.1547)
  line L3 (1, 0.5774) -> (1, -0.5774)
  line L4 (0, 1.1547) -> (1, 0.5774)
  line L5 (-1, 0.5774) -> (0, 1.1547)
  line L6 (-1, -0.5774) -> (-1, 0.5774)
  circle C1 centre (0, 0) radius 3
  point P1 (0, 0)
  point P9 (0, 0)
  coincident P1 P9
  vertical L6
  dimension "d12" distance L3 L6 = 2
extrude "Extrude1" cut sketch "Sketch2" profile of L1 L2 L3 L4 L5 L6 against normal blind 1.26

design "HW_M3x20-SHCS"
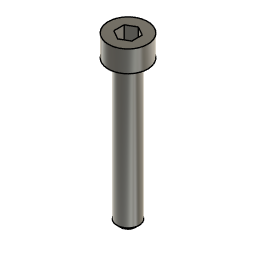
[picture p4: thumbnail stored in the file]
sketch "Sketch1" plane through (0, 0, 0) normal (0, 1, 0) x axis (1, 0, 0)
  line L1 (0, 20) -> (0, -3)
  line L2 (1.05, 20) -> (0, 20)
  line L3 (1.55, 19.5) -> (1.05, 20)
  line L4 (1.55, 0) -> (1.55, 19.5)
  line L5 (2.75, 0) -> (1.55, 0)
  line L6 (2.75, -3) -> (2.75, 0)
  line L7 (0, -3) -> (2.75, -3)
  point P1 (0, 0)
  point P4 (1.05, 20)
  point P5 (1.55, 19.5)
  point P3 (0, 20)
  point P7 (2.75, 0)
  point P8 (2.75, -3)
  point P2 (0, -3)
  vertical L1
  perpendicular L1 L2
  perpendicular L2 L4
  perpendicular L4 L5
  perpendicular L5 L6
  horizontal L7
  coincident P1 L1
  coincident P1 L5
  dimension "d1" distance P1 L2 = 20
  dimension "d2" angle L2 L3 = 45
  dimension "d3" distance P4 P5 = 0.5
  dimension "d4" distance P3 L4 = 1.55 (= "( 3.1 / 2 ) * 1 mm")
  dimension "d5" distance P7 P8 = 3
  dimension "d6" distance P2 P8 = 2.75 (= "( 5.5 / 2 ) * 1 mm")
revolve "Revolve1" sketch "Sketch1" AlongAngle 360
sketch "Sketch2" plane through (0, 0, 3) normal (0, 0, 1) x axis (-1, 0, 0)
  line L1 (0, -1.4434) -> (-1.25, -0.7217)
  line L2 (1.25, -0.7217) -> (0, -1.4434)
  line L3 (1.25, 0.7217) -> (1.25, -0.7217)
  line L4 (0, 1.4434) -> (1.25, 0.7217)
  line L5 (-1.25, 0.7217) -> (0, 1.4434)
  line L6 (-1.25, -0.7217) -> (-1.25, 0.7217)
  circle C1 centre (0, 0) radius 2.75
  point P1 (0, 0)
  point P9 (0, 0)
  point P5 (1.25, -0.7217)
  coincident P1 P9
  vertical L6
  dimension "d8" distance P5 L6 = 2.5
extrude "Extrude1" cut sketch "Sketch2" profile of L1 L2 L3 L4 L5 L6 against normal blind 2

design "HW_M5x10-SHCS"
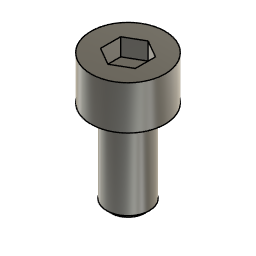
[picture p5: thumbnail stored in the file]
sketch "Sketch1" plane through (0, 0, 0) normal (0, 1, 0) x axis (1, 0, 0)
  line L1 (0, 10) -> (0, -5)
  line L2 (1.95, 10) -> (0, 10)
  line L3 (2.45, 9.5) -> (1.95, 10)
  line L4 (2.45, 0) -> (2.45, 9.5)
  line L5 (4.25, 0) -> (2.45, 0)
  line L6 (4.25, -5) -> (4.25, 0)
  line L7 (0, -5) -> (4.25, -5)
  point P1 (0, 0)
  point P4 (1.95, 10)
  point P5 (2.45, 9.5)
  point P3 (0, 10)
  point P7 (4.25, 0)
  point P8 (4.25, -5)
  point P2 (0, -5)
  vertical L1
  perpendicular L1 L2
  perpendicular L2 L4
  perpendicular L4 L5
  perpendicular L5 L6
  horizontal L7
  coincident P1 L1
  coincident P1 L5
  dimension "d1" distance P1 L2 = 10
  dimension "d2" angle L2 L3 = 45
  dimension "d3" distance P4 P5 = 0.5
  dimension "d4" distance P3 L4 = 2.45 (= "( 4.9 / 2 ) * 1 mm")
  dimension "d5" distance P7 P8 = 5
  dimension "d6" distance P2 P8 = 4.25 (= "( 8.5 / 2 ) * 1 mm")
revolve "Revolve1" sketch "Sketch1" AlongAngle 360
sketch "Sketch2" plane through (0, 0, 5) normal (0, 0, 1) x axis (-1, 0, 0)
  line L1 (0, -2.3094) -> (-2, -1.1547)
  line L2 (2, -1.1547) -> (0, -2.3094)
  line L3 (2, 1.1547) -> (2, -1.1547)
  line L4 (0, 2.3094) -> (2, 1.1547)
  line L5 (-2, 1.1547) -> (0, 2.3094)
  line L6 (-2, -1.1547) -> (-2, 1.1547)
  circle C1 centre (0, 0) radius 4.25
  point P1 (0, 0)
  point P9 (0, 0)
  point P5 (2, -1.1547)
  coincident P1 P9
  vertical L6
  dimension "d8" distance P5 L6 = 4
extrude "Extrude1" cut sketch "Sketch2" profile of L1 L2 L3 L4 L5 L6 against normal blind 2

design "circuit_modular_stepper"
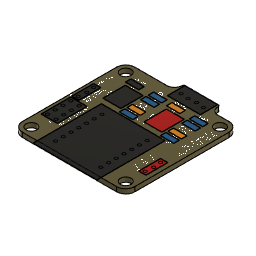
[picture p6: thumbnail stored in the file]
sketch "Outline" plane through (0, 0, 0) normal (0, 0, 1) x axis (1, 0, 0)
  line L1 (35, 1) -> (4, 1)
  line L2 (38, 35) -> (38, 4)
  line L3 (31, 38) -> (35, 38)
  line L4 (17.5, 41) -> (28.5, 41)
  line L5 (4, 38) -> (14.5, 38)
  line L6 (1, 4) -> (1, 35)
  arc A1 centre (4, 4) radius 3 clockwise from (4, 1) to (1, 4)
  arc A2 centre (35, 4) radius 3 clockwise from (38, 4) to (35, 1)
  arc A3 centre (35, 35) radius 3 clockwise from (35, 38) to (38, 35)
  arc A4 centre (31.25, 40.25) radius 2.2638 clockwise from (31, 38) to (29, 40.5)
  arc A5 centre (28.5, 40.5) radius 0.5 clockwise from (28.5, 41) to (29, 40.5)
  arc A6 centre (17.5, 40.5) radius 0.5 clockwise from (17, 40.5) to (17.5, 41)
  arc A7 centre (14.5, 40.5) radius 2.5 clockwise from (17, 40.5) to (14.5, 38)
  arc A8 centre (4, 35) radius 3 clockwise from (1, 35) to (4, 38)
canvas "Canvas1"
canvas "Canvas2"
pcbhole "PCBHole1" HoleDepth 1.606 HoleDiameter 3.5 TipAngle 10313.2
pcbhole "PCBHole2" HoleDepth 1.606 HoleDiameter 3.5 TipAngle 10313.2
pcbhole "PCBHole3" HoleDepth 1.606 HoleDiameter 3.5 TipAngle 10313.2
pcbhole "PCBHole4" HoleDepth 1.606 HoleDiameter 3.5 TipAngle 10313.2
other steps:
pcbextrude "PCBExtrude1"
pcbextrude "PCBExtrude1"
extrude "Extrude1" sketch "Outline" blind 1.5 bodies "Board"
box_primitive "BoxPrimitive1" DistanceX 7.1628 DistanceY 2.3368 DistanceZ 0.1 OffsetDistanceX 0 OffsetDistanceY 0
box_primitive "BoxPrimitive1" DistanceX 10.827 DistanceY 5.727 DistanceZ 0.1 OffsetDistanceX 0 OffsetDistanceY 0
box_primitive "BoxPrimitive1" DistanceX 5.353 DistanceY 9.7028 DistanceZ 0.1 OffsetDistanceX 0 OffsetDistanceY 0
box_primitive "BoxPrimitive1" DistanceX 4.4 DistanceY 1.8 DistanceZ 0.1 OffsetDistanceX 0 OffsetDistanceY 0
box_primitive "BoxPrimitive1" DistanceX 7.35 DistanceY 5.8597 DistanceZ 0.1 OffsetDistanceX 0 OffsetDistanceY 0
box_primitive "BoxPrimitive1" DistanceX 22.4638 DistanceY 20.955 DistanceZ 0.1 OffsetDistanceX 0 OffsetDistanceY 0
pcbextrude "PCBExtrude1"
pcbextrude "PCBExtrude2" bodies "CopperHoles"
create_component "CreateComponent1"
create_component "CreateComponent2"
create_component "CreateComponent3"
create_component "CreateComponent4"
create_component "CreateComponent1"
create_component "CreateComponent2"
create_component "CreateComponent3"
create_component "CreateComponent4"
create_component "CreateComponent5"
create_component "CreateComponent6"
as_built_joint "As-built1"
named bodies: "Board", "CopperHoles"

design "circuit_mount_stepper_simple" references "circuit_modular_stepper"
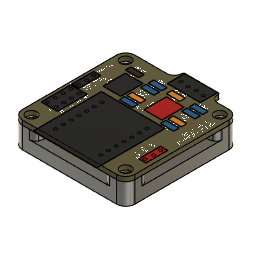
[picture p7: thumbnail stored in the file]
sketch "Sketch1" plane through (0, 0, 0) normal (0, 0, 1) x axis (1, 0, 0)
  line L1 (-18.5, 18.5) -> (18.5, 18.5)
  line L2 (-18.5, -18.5) -> (-18.5, 18.5)
  line L3 (18.5, -18.5) -> (-18.5, -18.5)
  line L4 (18.5, 18.5) -> (18.5, -18.5)
  line L5 (-18.5, -18.5) -> (18.5, 18.5)
  line L6 (18.5, -18.5) -> (-18.5, 18.5)
  line L7 (15.5, 15.5) -> (-15.5, 15.5)
  line L8 (15.5, -15.5) -> (15.5, 15.5)
  line L9 (-15.5, -15.5) -> (15.5, -15.5)
  line L10 (-15.5, 15.5) -> (-15.5, -15.5)
  circle C1 centre (15.5, 15.5) radius 1.7
  circle C2 centre (-15.5, 15.5) radius 1.7
  circle C3 centre (-15.5, -15.5) radius 1.7
  circle C4 centre (15.5, -15.5) radius 1.7
  circle C5 centre (-15.5, 15.5) radius 4.5
  circle C6 centre (15.5, 15.5) radius 4.5
  circle C7 centre (15.5, -15.5) radius 4.5
  circle C8 centre (-15.5, -15.5) radius 4.5
  circle C9 centre (0, 0) radius 15
  circle C10 centre (0, 0) radius 2.5
  circle C11 centre (0, 0) radius 4
  circle C12 centre (0, 0) radius 6.5
  point P6 (0, 0)
  point P1 (0, 0)
  point P9 (15.5, -15.5)
  point P7 (-15.5, 15.5)
  point P8 (15.5, 15.5)
  point P11 (15.5, 15.5)
  point P12 (-15.5, 15.5)
  point P10 (-15.5, -15.5)
  point P13 (-15.5, -15.5)
  point P14 (15.5, -15.5)
  point P19 (0, 0)
  point P21 (0, 0)
  point P2 (18.5, 18.5)
  point P3 (-18.5, 18.5)
  horizontal L1
  perpendicular L1 L2
  parallel L1 L3
  parallel L2 L4
  coincident L5 P6
  coincident L6 P6
  coincident P1 P6
  equal L1 L4
  horizontal L7
  vertical L8
  horizontal L9
  vertical L10
  coincident L6 P9
  coincident L6 P7
  coincident L5 P8
  equal C3 C4
  equal C1 C4
  equal C1 C2
  coincident P8 P11
  coincident P7 P12
  coincident P10 P13
  coincident P9 P14
  concentric C2 C5
  concentric C1 C6
  concentric C4 C7
  concentric C3 C8
  equal C5 C8
  equal C5 C6
  equal C6 C7
  coincident P1 P19
  concentric C9 C10
  coincident P1 P21
  concentric C9 C12
  dimension "d1" distance P7 P8 = 31
  dimension "d2" distance P2 P3 = 37
  dimension "d3" diameter C1 = 3.4
  dimension "d4" distance L4 P11 = 3
  dimension "d5" diameter C6 = 9
  dimension "d6" diameter C9 = 30
  dimension "d7" diameter C10 = 5
  dimension "d8" diameter C11 = 8
  dimension "d9" distance C11 C12 = 2.5
extrude "Extrude1" new body sketch "Sketch1" profile of L1 L2 L3 L4 C1 C2 C3 C4 C5 C6 C7 C8 along normal blind 7 bodies "circuit_mount_stepper_simple"
extrude "Extrude4" add sketch "Sketch1" profile of L1 L2 L3 L4 C5 C6 C7 C8 C9 to an object offset -3
chamfer "Chamfer4" distance 0.5
fillet "Fillet1" radius 3
fillet "Fillet2" radius 2
chamfer "Chamfer5" distance 0.5
component_insert "Component Insert"
joint "Assemble1" alignAngle 0 alignOffsetX 0 alignOffsetY 0 alignOffsetZ 0
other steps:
joint_origin "JointOrigin1"
named bodies: "circuit_mount_stepper_simple"

design "HW_M3x50-SHCS"
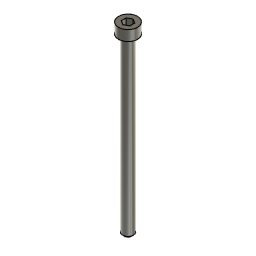
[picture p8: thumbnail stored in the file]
sketch "Sketch1" plane through (0, 0, 0) normal (0, 1, 0) x axis (1, 0, 0)
  line L1 (0, 50) -> (0, -3)
  line L2 (1.05, 50) -> (0, 50)
  line L3 (1.55, 49.5) -> (1.05, 50)
  line L4 (1.55, 0) -> (1.55, 49.5)
  line L5 (2.75, 0) -> (1.55, 0)
  line L6 (2.75, -3) -> (2.75, 0)
  line L7 (0, -3) -> (2.75, -3)
  point P1 (0, 0)
  point P4 (1.05, 50)
  point P5 (1.55, 49.5)
  point P3 (0, 50)
  point P7 (2.75, 0)
  point P8 (2.75, -3)
  point P2 (0, -3)
  vertical L1
  perpendicular L1 L2
  perpendicular L2 L4
  perpendicular L4 L5
  perpendicular L5 L6
  horizontal L7
  coincident P1 L1
  coincident P1 L5
  dimension "d1" distance P1 L2 = 50
  dimension "d2" angle L2 L3 = 45
  dimension "d3" distance P4 P5 = 0.5
  dimension "d4" distance P3 L4 = 1.55 (= "( 3.1 / 2 ) * 1 mm")
  dimension "d5" distance P7 P8 = 3
  dimension "d6" distance P2 P8 = 2.75 (= "( 5.5 / 2 ) * 1 mm")
revolve "Revolve1" sketch "Sketch1" AlongAngle 360
sketch "Sketch2" plane through (0, 0, 3) normal (0, 0, 1) x axis (-1, 0, 0)
  line L1 (0, -1.4434) -> (-1.25, -0.7217)
  line L2 (1.25, -0.7217) -> (0, -1.4434)
  line L3 (1.25, 0.7217) -> (1.25, -0.7217)
  line L4 (0, 1.4434) -> (1.25, 0.7217)
  line L5 (-1.25, 0.7217) -> (0, 1.4434)
  line L6 (-1.25, -0.7217) -> (-1.25, 0.7217)
  circle C1 centre (0, 0) radius 2.75
  point P1 (0, 0)
  point P9 (0, 0)
  point P5 (1.25, -0.7217)
  coincident P1 P9
  vertical L6
  dimension "d8" distance P5 L6 = 2.5
extrude "Extrude1" cut sketch "Sketch2" profile of L1 L2 L3 L4 L5 L6 against normal blind 2

design "PP_SWTC_Omron-V154"
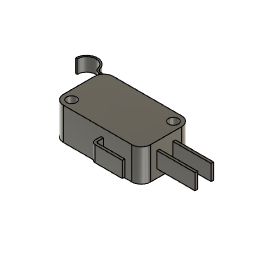
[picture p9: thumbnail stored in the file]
sketch "Sketch1" plane through (0, 0, 0) normal (0, 0, 1) x axis (1, 0, 0)
  line L1 (22.2, 0) -> (0, 0)
  line L2 (22.2, 10.3) -> (22.2, 0)
  line L3 (0, 10.3) -> (22.2, 10.3)
  line L4 (0, 0) -> (0, 10.3)
  line L5 (25, -2.8) -> (-2.8, -2.8)
  line L6 (25, 13.1) -> (25, -2.8)
  line L7 (-2.8, 13.1) -> (25, 13.1)
  line L8 (-2.8, -2.8) -> (-2.8, 13.1)
  line L9 (14.1, 15.2) -> (14.1, 13.1)
  line L10 (-6.9, 15.2) -> (14.1, 15.2)
  line L11 (13.6, 14.7) -> (-7.442, 14.7)
  line L12 (13.6, 13.1) -> (13.6, 14.7)
  line L13 (-13.9, 15.2) -> (-13.4, 15.2)
  line L14 (-10.4, 18.7) -> (-10.4, 15.2)
  line L15 (37.2, 8.1) -> (25, 8.1)
  line L16 (37.2, 7.3) -> (37.2, 8.1)
  line L17 (25, 7.3) -> (37.2, 7.3)
  line L18 (25, 8.1) -> (25, 7.3)
  line L19 (37.2, 3) -> (25, 3)
  line L20 (37.2, 2.2) -> (37.2, 3)
  line L21 (25, 2.2) -> (37.2, 2.2)
  line L22 (25, 3) -> (25, 2.2)
  line L23 (13, -5.2) -> (13, -2.8)
  line L24 (22.2, -5.2) -> (13, -5.2)
  line L25 (22.2, -6) -> (22.2, -5.2)
  line L26 (12.2, -6) -> (22.2, -6)
  line L27 (12.2, -2.8) -> (12.2, -6)
  circle C1 centre (0, 0) radius 2.8
  circle C2 centre (22.2, 10.3) radius 2.8
  circle C3 centre (22.2, 10.3) radius 1.55
  circle C4 centre (0, 0) radius 1.55
  arc A1 centre (-10.4, 15.2) radius 3.5 clockwise from (-13.9, 15.2) to (-6.9, 15.2)
  arc A2 centre (-10.4, 15.2) radius 3 clockwise from (-13.4, 15.2) to (-7.442, 14.7)
  point P1 (0, 0)
  point P2 (0, 0)
  point P10 (0, 0)
  point P4 (22.2, 10.3)
  point P11 (22.2, 10.3)
  point P13 (0, 0)
  point P14 (14.1, 13.1)
  point P18 (-13.9, 15.2)
  point P17 (-10.4, 15.2)
  point P19 (-10.4, 15.2)
  point P23 (13.6, 13.1)
  point P24 (-10.4, 15.2)
  point P25 (-10.4, 18.7)
  point P26 (25, 8.1)
  point P30 (25, 3)
  point P34 (13, -2.8)
  point P39 (12.2, -2.8)
  point P31 (37.2, 3)
  point P3 (22.2, 0)
  point P6 (-2.8, -2.8)
  point P7 (25, -2.8)
  point P9 (-2.8, 13.1)
  point P8 (25, 13.1)
  point P12 (22.2, 10.3)
  point P22 (13.6, 14.7)
  point P15 (14.1, 15.2)
  point P35 (13, -5.2)
  point P32 (37.2, 2.2)
  point P27 (37.2, 8.1)
  point P28 (37.2, 7.3)
  point P37 (22.2, -6)
  horizontal L1
  vertical L2
  horizontal L3
  vertical L4
  coincident P1 P2
  horizontal L5
  vertical L6
  horizontal L7
  vertical L8
  coincident P1 P10
  coincident P4 P11
  concentric C2 C3
  coincident P1 P13
  equal C3 C4
  tangent L7 C2
  tangent L6 C2
  tangent L5 C1
  coincident L7 P14
  perpendicular L7 L9
  perpendicular L9 L10
  coincident L10 P18
  coincident P17 P19
  horizontal L11
  coincident L7 P23
  perpendicular L7 L12
  coincident P19 L13
  horizontal L13
  coincident P19 P24
  midpoint A1 P25
  horizontal L15
  vertical L16
  horizontal L17
  vertical L18
  coincident L6 P26
  horizontal L19
  vertical L20
  horizontal L21
  vertical L22
  coincident L6 P30
  coincident L5 P34
  perpendicular L5 L23
  perpendicular L6 L24
  perpendicular L24 L25
  perpendicular L25 L26
  coincident L5 P39
  perpendicular L5 L27
  coincident L16 P31
  dimension "d2" distance P2 P3 = 22.2
  dimension "d3" distance P3 P4 = 10.3
  dimension "d4" distance P6 P7 = 27.8
  dimension "d5" distance P6 P9 = 15.9
  dimension "d6" diameter C3 = 3.1
  dimension "d7" distance P8 P12 = 2.8
  dimension "d8" distance L9 L12 = 0.5
  dimension "d9" distance L10 P22 = 0.5 (= "d8")
  dimension "d10" distance A1 A2 = 0.5 (= "d8")
  dimension "d11" radius A1 = 3.5
  dimension "d12" distance P10 P25 = 18.7
  dimension "d13" distance P12 P25 = 32.6
  dimension "d14" distance P12 P15 = 8.1
  dimension "d25" distance P35 L27 = 0.8
  dimension "d26" distance P35 L26 = 0.8 (= "d25")
  dimension "d27" distance P31 P32 = 0.8 (= "d25")
  dimension "d28" distance P27 P28 = 0.8 (= "d25")
  dimension "d29" distance P8 P37 = 19.1
  dimension "d30" distance P7 P37 = 2.8
  dimension "d31" distance P7 L23 = 12
  dimension "d33" distance P8 P27 = 5
  dimension "d34" distance P6 P28 = 40
  dimension "d35" distance P7 P32 = 5 (= "d33")
extrude "Extrude1" new body sketch "Sketch1" profile of L5 L6 L7 L8 C3 C4 distance 10.3
extrude "Extrude2" add sketch "Sketch1" profile of L7 L9 L10 A1 A2 L11 L12 L13 distance 4.3
fillet "Fillet1" radius 3
fillet "Fillet2" radius 1
fillet "Fillet3" radius 1.5
extrude "Extrude3" add sketch "Sketch1" profile of L5 L6 L15 L16 L17 L18 L19 L20 L21 L22 L23 L24 L25 L26 L27 distance 5
fillet "Fillet4" radius 0.5
fillet "Fillet5" radius 1.3 (= "0.5 mm + 0.8 mm")

design "HW_M3-Washer"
